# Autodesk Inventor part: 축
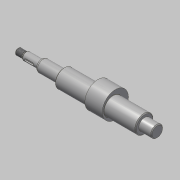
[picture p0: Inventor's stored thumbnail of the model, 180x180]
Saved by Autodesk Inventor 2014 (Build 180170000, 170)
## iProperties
Created: 2015-12
Part Number: 축
Document SubType Name: Modeling
Designer: mdu
Density: 7.86 g/cm^3
Material: 강철, 연강
Appearance: 강철
Mass: 484.681 g
Surface Area: 125.968 cm^2
Volume: 61.6642 cm^3
Author: mdu
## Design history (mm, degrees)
sketch "스케치1"
  geometry: L1 (62, 100.9)-(62, 67.1) reference; L2 (51, 101.2)-(51, 84) reference; L3 (-51, 84)-(-51, 101.2) reference; L4 (-62, 67.1)-(-62, 100.9) reference; L5 (-51.6, 91.5)-(-61.4, 91.5) reference; L6 (51.6, 91.5)-(61.4, 91.5) reference; L7 (67, 84)-(-109, 84); L8 (-77, 64.201)-(-77, 103.799) reference; L9 (67, 84)-(67, 91.5); L10 (67, 91.5)-(51, 91.5); L11 (51, 91.5)-(51, 95.5); L12 (51, 95.5)-(-51, 95.5); L13 (-51, 95.5)-(-51, 91.5); L14 (-51, 91.5)-(-79, 91.5); L15 (-79, 91.5)-(-79, 89); L16 (-79, 89)-(-99, 89); L17 (-99, 89)-(-99, 87); L18 (-100.5, 88)-(-109, 88); L19 (-109, 88)-(-109, 84); L20 (-99, 87)-(-100.5, 87); L21 (-100.5, 87)-(-100.5, 88); 2 further points
  constraints: 32 end point, 7 parallel, 6 point on line, 5 perpendicular, 2 collinear, 2 horizontal, 1 midpoint, 4 other
  dimensions: "d0" = 5 distance from line of L7.start L1; "d2" = 2 distance between parallel lines of L15 L8; "d3" = 23 diameter of L12 L7; "d4" = 10 diameter of L16 L7; "d5" = 1.5 distance of L17.end L20.end; "d6" = 6 diameter of L20 L7; "d7" = 20 distance of L15.end L16.end; "d8" = 10 distance between parallel lines of L17 L19; "d9" = 8 diameter of L18 L7
revolve "회전1" sketch "스케치1" stored, may be unused: angle "d10" = 90 deg
sketch "스케치2"
  geometry: C1 r 11.5 at (84, 0) reference; C2 r 11.5 at (84, 0) reference; C3 r 16.5 at (87, 0); 1 further point
  constraints: 1 centre point, 1 horizontal alignment
  dimensions: "d11" = 33 diameter of C3; "d12" = 3 distance of C3.centre C1.centre
extrude "돌출1" join sketch "스케치2" stored distance "d13" = 22; taper "d14" = 0 deg
chamfer "모따기1" distance "d15" = 1; stored, may be unused: second distance "d16" = 2, angle "d17" = 45 deg
feature "스레드1" dims "d18" = 10, "d19" = 0
node "작업 평면1"
sketch "스케치3"
  geometry: L1 (-5.5, -1.5)-(3.5, -1.5); L2 (3.5, 1.5)-(-5.5, 1.5); L3 (-10, -4)-(-10, 4) reference; A1 r 1.5 centre (3.5, 0) between (3.5, -1.5) and (3.5, 1.5); A2 r 1.5 centre (-5.5, 0) between (-5.5, 1.5) and (-5.5, -1.5); 2 further points
  constraints: 4 end point, 4 point on circle, 4 tangent, 2 centre point, 1 horizontal, 1 horizontal alignment, 1 midpoint, 1 parallel
  dimensions: "d20" = 3 distance between parallel lines of L1 L2; "d21" = 12 dimension on A1 A2; "d22" = 3 distance edge to line of A2 L3
extrude "돌출2" cut sketch "스케치3" distance "d23" = 1.8; taper "d24" = 0 deg
fillet "모깎기1" dims "d25" = 0.3
fillet "모깎기2" dims "d26" = 3
node "솔리드1"
node "참조1"
node "참조2"
node "참조3"
node "참조4"
node "참조5"
node "투영된 루프1"
